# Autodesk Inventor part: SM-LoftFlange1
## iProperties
Created: 2008-12
Part Number: SM-LoftFlange1
Material: Default
Document SubType Name: Sheet Metal
Designer: Designer
Density: 1 g/cm^3
Sheet Metal Rule: Default_mm
Author: Designer
